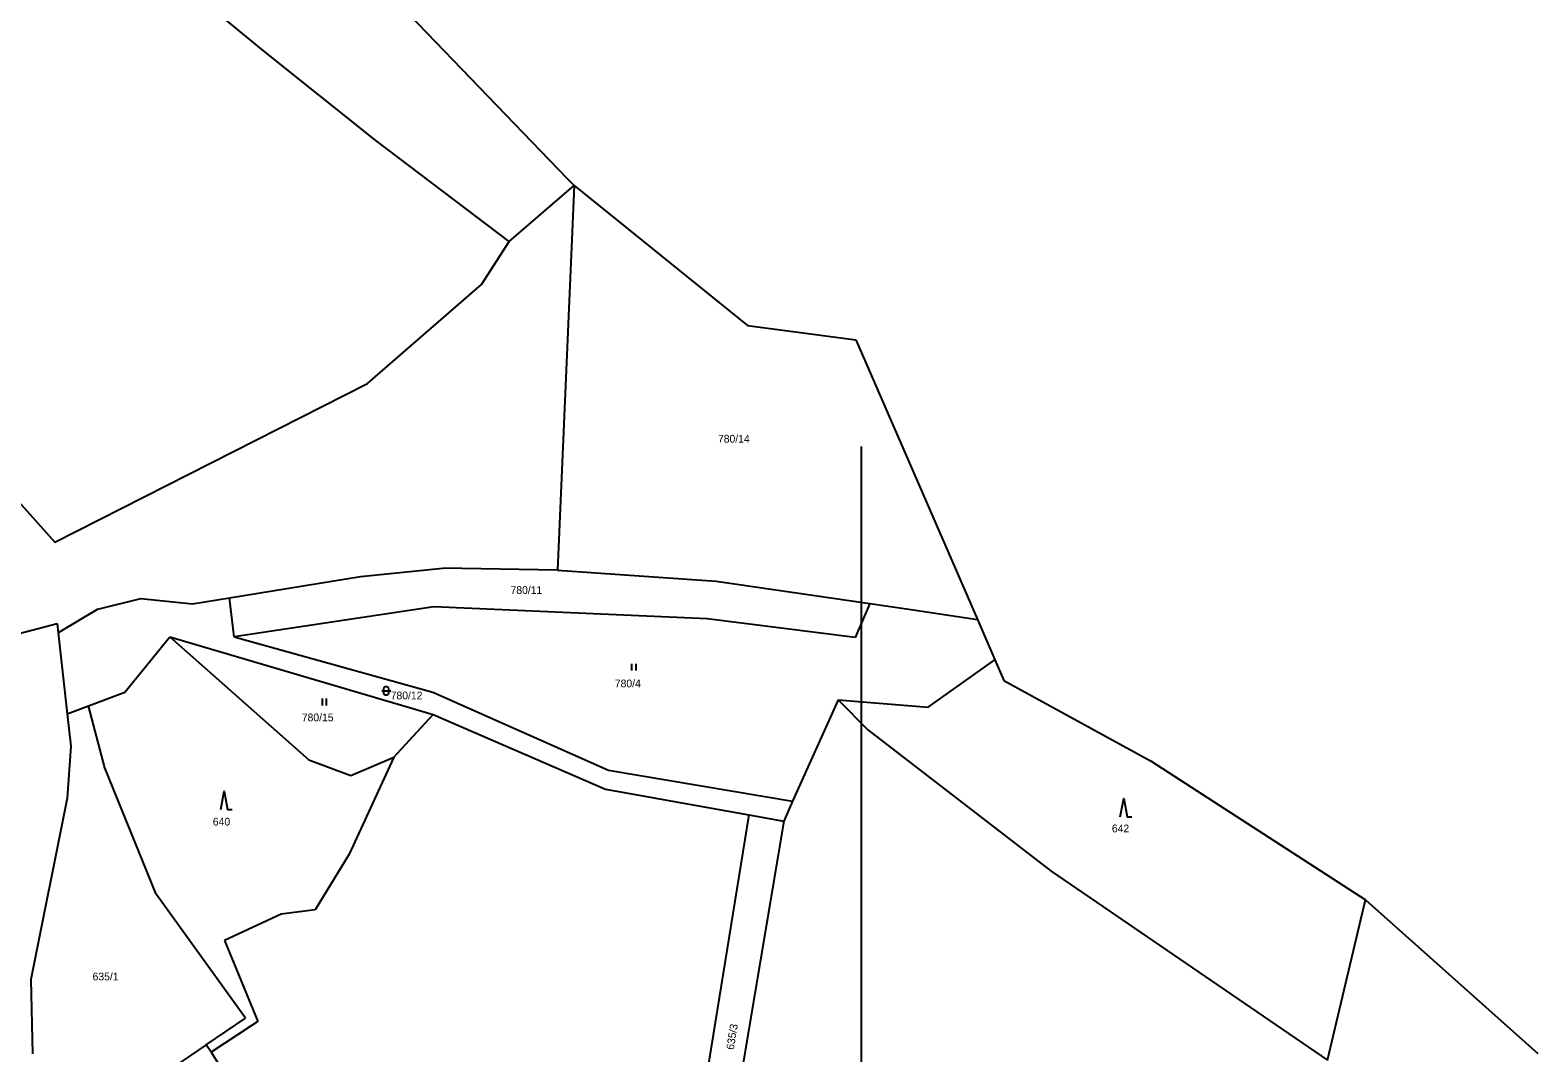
# Model space of a CAD drawing. Extents: x -801907 to -800293, y -1017000 to -1015684.
# Drawn here: x -800807.1 to -800476.8, y -1016132.8 to -1015908.8 of the extents above; entities that cross this region are included whole.
import ezdxf

# ---------------------------------------------------------------- set-up
doc = ezdxf.new("R2010")
doc.units = 0
for name, color, linetype in [('Default', 7, 'Continuous'), ('KLADY_ZMVM', 7, 'Continuous'), ('KN_HRANICE', 7, 'Continuous'), ('KN_KULTURY', 7, 'Continuous'), ('KN_PARCELY', 7, 'Continuous')]:
    doc.layers.add(name, color=color, linetype=linetype)

# ---------------------------------------------------------------- blocks, each defined once
blk = doc.blocks.new('306')
at = {"layer": 'Default'}
for p, q in [((-0.5, 1.5), (-0.5, 0)), ((0.5, 0), (0.5, 1.5))]:
    blk.add_line(p, q, dxfattribs=at)
blk = doc.blocks.new('308')
at = {"layer": 'Default'}
blk.add_lwpolyline([(-0.75, 0), (0, 4), (0.75, 0), (1.75, 0)], dxfattribs=at)
blk = doc.blocks.new('316')
at = {"layer": 'Default'}
for points in [[(-1, 1), (0.27, 1), (1, 1)], [(-0.5, 1.5), (-0.4, 1.79), (-0.15, 1.97), (0.16, 1.97), (0.41, 1.79), (0.51, 1.5), (0.51, 0.5), (0.41, 0.21), (0.16, 0.03), (-0.15, 0.03), (-0.4, 0.21), (-0.5, 0.5), (-0.5, 1.5)]]:
    blk.add_lwpolyline(points, dxfattribs=at)

msp = doc.modelspace()

# ---------------------------------------------------------------- linework, layer by layer
at = {"layer": 'KLADY_ZMVM'}
msp.add_lwpolyline([(-800625, -1016000), (-800625, -1016500), (-800625, -1017000)], dxfattribs=at)
at = {"layer": 'KN_HRANICE'}
for p, q in [((-800730.51, -1015898.56), (-800689.48, -1015941.19)), ((-800756.01, -1015913.25), (-800769.79, -1015901.81)), ((-800731.31, -1015932.96), (-800756.01, -1015913.25)), ((-800702.15, -1015955.09), (-800731.31, -1015932.96)), ((-800702.15, -1015955.09), (-800687.91, -1015942.82)), ((-800687.91, -1015942.82), (-800691.57, -1016027.07)), ((-800689.48, -1015941.19), (-800687.91, -1015942.82)), ((-800687.91, -1015942.82), (-800649.96, -1015973.49)), ((-800708.23, -1015964.5), (-800702.15, -1015955.09)), ((-800733.15, -1015986.18), (-800708.23, -1015964.5)), ((-800649.96, -1015973.49), (-800626.22, -1015976.61)), ((-800626.22, -1015976.61), (-800599.58, -1016037.93)), ((-800801.68, -1016020.93), (-800733.15, -1015986.18)), ((-800826.83, -1015992.84), (-800801.68, -1016020.93)), ((-800763.42, -1016033.13), (-800734.7, -1016028.44)), ((-800734.7, -1016028.44), (-800716.7, -1016026.66)), ((-800691.57, -1016027.07), (-800716.7, -1016026.66)), ((-800691.57, -1016027.07), (-800656.81, -1016029.48)), ((-800656.81, -1016029.48), (-800623.14, -1016034.39)), ((-800792.26, -1016035.61), (-800800.93, -1016040.79)), ((-800792.26, -1016035.61), (-800782.84, -1016033.31)), ((-800782.84, -1016033.31), (-800771.53, -1016034.46)), ((-800771.53, -1016034.46), (-800763.42, -1016033.13)), ((-800762.37, -1016041.73), (-800763.42, -1016033.13)), ((-800718.61, -1016035.13), (-800762.37, -1016041.73)), ((-800658.78, -1016037.74), (-800718.61, -1016035.13)), ((-800623.14, -1016034.39), (-800626.32, -1016041.82)), ((-800623.14, -1016034.39), (-800615.13, -1016035.56)), ((-800615.13, -1016035.56), (-800599.58, -1016037.93)), ((-800812.57, -1016041.79), (-800801.16, -1016038.76)), ((-800801.16, -1016038.76), (-800800.93, -1016040.79)), ((-800626.32, -1016041.82), (-800658.78, -1016037.74)), ((-800599.58, -1016037.93), (-800595.76, -1016046.73)), ((-800800.93, -1016040.79), (-800798.96, -1016058.55)), ((-800786.31, -1016053.81), (-800776.47, -1016041.66)), ((-800776.47, -1016041.66), (-800746.03, -1016068.65)), ((-800776.47, -1016041.66), (-800718.78, -1016058.74)), ((-800762.37, -1016041.73), (-800718.83, -1016053.85)), ((-800610.33, -1016057.07), (-800595.76, -1016046.73)), ((-800595.76, -1016046.73), (-800593.79, -1016051.26)), ((-800593.79, -1016051.26), (-800561.5, -1016068.96)), ((-800794.32, -1016056.81), (-800786.31, -1016053.81)), ((-800718.83, -1016053.85), (-800680.37, -1016070.94)), ((-800630.08, -1016055.49), (-800640.04, -1016077.67)), ((-800630.08, -1016055.49), (-800610.33, -1016057.07)), ((-800630.08, -1016055.49), (-800623.6, -1016062.07)), ((-800798.96, -1016058.55), (-800794.32, -1016056.81)), ((-800798.96, -1016058.55), (-800798.15, -1016065.67)), ((-800790.73, -1016070.43), (-800794.32, -1016056.81)), ((-800727.37, -1016068.06), (-800718.78, -1016058.74)), ((-800718.78, -1016058.74), (-800681.02, -1016075.08)), ((-800623.6, -1016062.07), (-800583.45, -1016093.02)), ((-800798.15, -1016065.67), (-800798.97, -1016077.03)), ((-800746.03, -1016068.65), (-800736.79, -1016072.04)), ((-800727.37, -1016068.06), (-800737.18, -1016089.33)), ((-800736.79, -1016072.04), (-800727.37, -1016068.06)), ((-800561.5, -1016068.96), (-800514.57, -1016099.34)), ((-800779.49, -1016098.06), (-800790.73, -1016070.43)), ((-800680.37, -1016070.94), (-800640.04, -1016077.67)), ((-800681.02, -1016075.08), (-800649.62, -1016080.7)), ((-800798.97, -1016077.03), (-800806.9, -1016116.78)), ((-800640.04, -1016077.67), (-800642.01, -1016082.06)), ((-800649.62, -1016080.7), (-800658.77, -1016137)), ((-800642.01, -1016082.06), (-800650.89, -1016135.02)), ((-800649.62, -1016080.7), (-800642.01, -1016082.06)), ((-800737.18, -1016089.33), (-800744.66, -1016101.5)), ((-800583.45, -1016093.02), (-800522.87, -1016134.41)), ((-800759.86, -1016125.22), (-800779.49, -1016098.06)), ((-800744.66, -1016101.5), (-800752.05, -1016102.49)), ((-800522.87, -1016134.41), (-800514.57, -1016099.34)), ((-800514.57, -1016099.34), (-800476.81, -1016132.98)), ((-800752.05, -1016102.49), (-800764.51, -1016108.23)), ((-800764.51, -1016108.23), (-800757.19, -1016125.94)), ((-800806.9, -1016116.78), (-800806.54, -1016133.07)), ((-800768.52, -1016131.08), (-800759.86, -1016125.22)), ((-800758.66, -1016126.91), (-800767.44, -1016132.7)), ((-800757.19, -1016125.94), (-800758.66, -1016126.91)), ((-800768.52, -1016131.08), (-800778.84, -1016138.06)), ((-800767.44, -1016132.7), (-800768.52, -1016131.08)), ((-800767.44, -1016132.7), (-800746.19, -1016166.34))]:
    msp.add_line(p, q, dxfattribs=at)

# ---------------------------------------------------------------- block references
at = {"layer": 'KN_KULTURY'}
for name, p in [('306', (-800674.82, -1016049.08)), ('316', (-800729.06, -1016054.54)), ('306', (-800742.62, -1016056.72)), ('308', (-800764.58, -1016079.5)), ('308', (-800567.52, -1016081.11))]:
    msp.add_blockref(name, p, dxfattribs=at)

# ---------------------------------------------------------------- texts
at = {"layer": 'KN_PARCELY'}
for s, p in [('780/14', (-800656.4, -1015999.14)), ('780/11', (-800701.84, -1016032.3)), ('780/4', (-800678.99, -1016052.76)), ('780/12', (-800728.09, -1016055.39)), ('780/15', (-800747.56, -1016060.2)), ('640', (-800767.05, -1016083.04)), ('642', (-800570.12, -1016084.52)), ('635/1', (-800793.39, -1016116.96))]:
    msp.add_text(s, height=1.7, dxfattribs=at).set_placement(p)
msp.add_text('635/3', height=1.7, rotation=81.016, dxfattribs=at).set_placement((-800652.93, -1016132.26))

doc.saveas('drawing.dxf')
